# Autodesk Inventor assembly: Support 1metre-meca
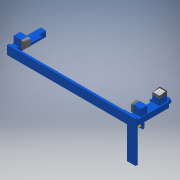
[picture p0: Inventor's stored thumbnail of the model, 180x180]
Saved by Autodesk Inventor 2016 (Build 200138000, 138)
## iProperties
Shininess: 41.0
Angle Display Precision: 2
Document Length Units: 11269
Document Angle Units: 11279
Document Time Units: 11290
Document Mass Units: 11283
Document Length Units Precision: 3
Document Angle Units Precision: 2
Created: 2002-09
Part Number: Support 1metre-meca
Document SubType Name: Assemblage
Designer: administrateur
Density: 0.0
Volumn: 0.0
Area: 0.0
PropertySet Name: Model Information
Control State: 0
Master: False
Checked Out: False
Author: administrateur
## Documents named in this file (4)
- D:\Cours\1-Cours-2016-17\1Ssi\5. Statique\FAAC\Portail\Support 1metre-meca.iam
- D:\Cours\1-Cours-2016-17\1Ssi\5. Statique\FAAC\Portail\Vis support arrière.ipt
- D:\Cours\1-Cours-2016-17\1Ssi\5. Statique\FAAC\Portail\Ecrou support arrière.ipt
- D:\Cours\1-Cours-2016-17\1Ssi\5. Statique\FAAC\Portail\Support 1metre.iam
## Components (3 placed, 3 different names)
1. Support 1metre:1 [sub-assembly]
2. Ecrou support arrière:1 — Plaquage:11
3. Vis support arrière:1 — Plaquage:11
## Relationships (1: Mate 1)
- Plaquage:11 [Mate]: Ecrou support arrière:1 ↔ Vis support arrière:1
